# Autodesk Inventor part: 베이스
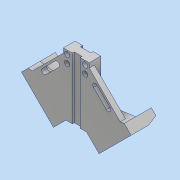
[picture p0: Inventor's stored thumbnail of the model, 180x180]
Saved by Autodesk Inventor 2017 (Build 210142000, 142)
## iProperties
Part Number: 베이스
Material: 알루미늄 6061
Document SubType Name: Modeling
Designer: mrc
Density: 2.7 g/cm^3
Appearance: 알루미늄 - 평지
Mass: 571.54 g
Surface Area: 407.272 cm^2
Volume: 211.682 cm^3
Author: mrc
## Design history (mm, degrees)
sketch "스케치1"
  geometry: L1 (84.853, 0)-(0, -84.853); L2 (0, -84.853)-(-84.853, 0); L3 (-84.853, 0)-(0, 84.853); L4 (0, 84.853)-(84.853, 0); L5 (20, 64.853)-(-20, 64.853); L6 (35.355, -49.497)-(16.005, -30.147); L7 (16.005, -30.147)-(-16.005, -30.147); L8 (-16.005, -30.147)-(-35.355, -49.497); L9 (-24.749, -38.891)-(-74.246, 10.607); L10 (-74.246, 10.607)-(-49.497, 7.071); L11 (-49.497, 7.071)-(-20, 36.569); L12 (-20, 36.569)-(-20, 64.853); L13 (-29.698, 38.184)-(-49.497, 18.385); L14 (-32.527, 41.012)-(-52.326, 21.213); L15 (-46.669, 15.556)-(-26.87, 35.355); A1 r 4 centre (-29.698, 38.184) between (-26.87, 35.355) and (-32.527, 41.012); A2 r 4 centre (-49.497, 18.385) between (-52.326, 21.213) and (-46.669, 15.556); 3 further points
  constraints: 32 end point, 6 point on line, 4 parallel, 4 point on circle, 4 tangent, 2 centre point, 2 horizontal, 2 perpendicular, 1 coincident, 1 horizontal alignment, 1 midpoint, 1 vertical, 1 vertical alignment, 9 other
  dimensions: "d0" = 120 distance of L1.end L2.end; "d1" = 20 distance from line of L3.end L5; "d2" = 50 distance from line of L1.end L8; "d3" = 95 distance between parallel lines of L7 L5; "d4" = 15 distance between parallel lines of L2 L9; "d5" = 20 distance between parallel lines of L11 L3; "d6" = 30 distance from line of L10.end L2; "d7" = 28 distance of L13.start L13.end; "d8" = 38 distance from line of L2 L13.end; "d9" = 12 distance between parallel lines of L13 L3; "d10" = 4 radius of A2
extrude "돌출1" new body sketch "스케치1" distance "d11" = 18; taper "d12" = 0 deg
extrude "돌출2" join sketch "스케치1" distance "d13" = 24; taper "d14" = 0 deg
extrude "돌출3" cut sketch "스케치1" stored distance "d15" = 24; taper "d16" = 0 deg
extrude "돌출4" cut sketch "스케치1" distance "d17" = 10; taper "d18" = 0 deg
sketch "스케치2"
  geometry: L1 (0, 42)-(-15, 42) reference; L2 (-5, 42)-(0, 27); L3 (0, 0)-(0, 42) reference; 1 further point
  constraints: 2 end point, 2 point on line
  dimensions: "d19" = 15 vertical distance of L2.start L2.end; "d20" = 5 horizontal distance of L2.start L2.end
extrude "돌출5" cut sketch "스케치2" stored distance "d21" = 10; taper "d22" = 0 deg
sketch "스케치3"
  geometry: L1 (14, 3)-(26, 3); L2 (26, 3)-(26, 0); L3 (26, 0)-(14, 0); L4 (14, 0)-(14, 3); L5 (12, 18)-(28, 18); L6 (28, 18)-(28, 14.5); L7 (28, 14.5)-(12, 14.5); L8 (12, 14.5)-(12, 18); L9 (0, 18)-(40, 18) reference; L10 (40, 0)-(0, 0) reference; 3 further points
  constraints: 16 end point, 4 midpoint, 4 parallel, 2 horizontal, 2 perpendicular
  dimensions: "d23" = 12 distance of L2.end L3.end; "d24" = 3 distance of L1.end L2.end; "d25" = 16 distance of L6.end L7.end; "d26" = 3.5 distance of L5.end L6.end
extrude "돌출6" cut sketch "스케치3" stored distance "d27" = 10; taper "d28" = 0 deg
sketch "스케치4"
  geometry: L1 (20, 64.853)-(6, 64.853) reference; 3 further points
  constraints: 1 vertical alignment
  dimensions: "d29" = 12 distance of point (14, 46.853) point (14, 58.853); "d30" = 6 distance from line of point (14, 58.853) L1; "d31" = 14 horizontal distance of point (0, 0) point (14, 58.853)
hole "구멍1" sketch "스케치4" at (14, 58.853), (14, 46.853) diameter "d32" = 4.5; stored, may be unused: countersink angle "d36" = 90 deg, drill point angle "d38" = 118 deg; dims "d33" = 6, "d34" = 8, "d35" = 10, "d37" = 8
sketch "스케치5"
  geometry: L1 (-15, 0)-(-15, 70) reference; L2 (0, 70)-(0, 0) reference; L3 (-15, 70)-(-10, 70) reference; 2 further points
  constraints: 1 other
  dimensions: "d39" = 5 distance from line of point (-5, 35) L2; "d40" = 35 distance from line of point (-5, 35) L3
feature "엠보싱1" sketch "스케치5" dims "d0" = 120, "d1" = 20, "d2" = 50, "d3" = 95, "d4" = 15, "d5" = 20, "d6" = 30, "d7" = 28, "d8" = 38, "d9" = 12, "d10" = 4, "d41" = 0.5, "d42" = 0
sketch "스케치6"
  geometry: L1 (68.059, -9.723)-(20, -57.782); L2 (74.246, -10.607)-(20, -64.853) reference; L3 (49.497, -7.071)-(74.246, -10.607) reference; L4 (20, -64.853)-(20, -36.569) reference; 1 further point
  constraints: 2 end point, 2 point on line, 1 parallel
  dimensions: "d43" = 5 distance between parallel lines of L2 L1
extrude "돌출7" cut sketch "스케치6" stored distance "d44" = 10; taper "d45" = 0 deg
fillet "모깎기1" dims "d46" = 5
node "솔리드1"
mirror "미러1"
mirror "미러2"
mirror "미러3"
mirror "미러4"
